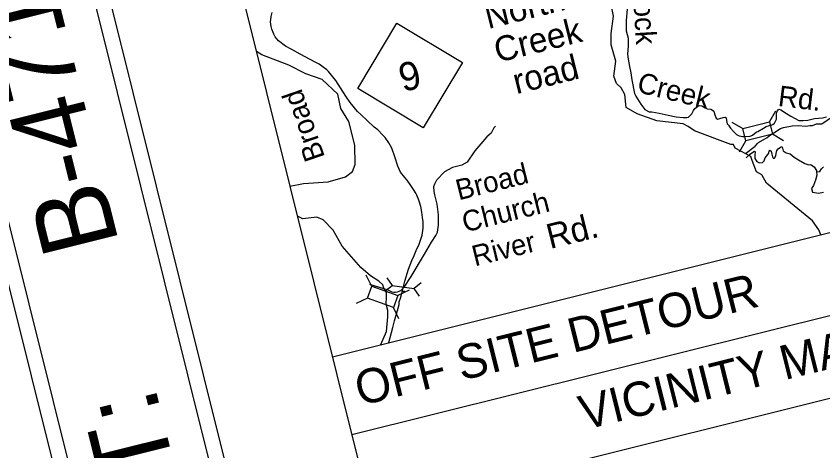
# Model space of a CAD drawing. Extents: x 1030323 to 1034123, y 654802 to 657751.
# Drawn here: x 1030543.2 to 1030807.6, y 656699.4 to 656841.8 of the extents above; entities that cross this region are included whole.
import ezdxf

# ---------------------------------------------------------------- set-up
doc = ezdxf.new("R2010")
doc.units = 0
for name, color, linetype in [('COGO Default Parcel', 7, 'Continuous'), ('Default', 7, 'Continuous'), ('Prop Dimension', 7, 'Continuous'), ('Prop Shade Light', 7, 'Continuous'), ('Sheet Title CELL', 7, 'Continuous')]:
    doc.layers.add(name, color=color, linetype=linetype)

msp = doc.modelspace()

# ---------------------------------------------------------------- linework, layer by layer
at = {"layer": 'COGO Default Parcel'}
for points in [[(1030763.46, 656805.71), (1030761.88, 656806.58), (1030753.15, 656807.52), (1030746.75, 656809.86), (1030743.2, 656811.93), (1030742.76, 656816.18), (1030741.52, 656818.34), (1030739.98, 656819.77), (1030739.15, 656822.21), (1030739.79, 656827.13), (1030738.2, 656832.4), (1030738.18, 656836.13), (1030738.96, 656841.88), (1030737.95, 656847.35), (1030734.88, 656851.54), (1030733.68, 656854.21), (1030732.33, 656861.16), (1030732.26, 656862.62), (1030731.76, 656863.61)], [(1030743.47, 656844.15), (1030743.19, 656840.4), (1030743.14, 656836.97), (1030743.76, 656834.57), (1030743.8, 656832.07), (1030743.61, 656829.36), (1030743.83, 656827.78), (1030744.26, 656825.33), (1030744.64, 656823.28), (1030745.01, 656820.98), (1030745.86, 656816.5), (1030746.32, 656815.6), (1030747.91, 656813.02), (1030749.3, 656811.27), (1030750.72, 656810.52), (1030751.58, 656810.48), (1030753.93, 656810.03), (1030756.89, 656809.38), (1030759.52, 656808.88), (1030761.86, 656808.63), (1030763.02, 656808.62), (1030763.59, 656808.78), (1030764.62, 656809.81), (1030765.22, 656810.88), (1030765.7, 656811.57), (1030766.53, 656812.27), (1030767.2, 656812.51), (1030767.99, 656812.49), (1030769.05, 656811.85), (1030769.75, 656811.51), (1030770.85, 656811.41), (1030771.46, 656811.04), (1030771.86, 656810.66), (1030772.25, 656809.46), (1030772.62, 656808.44), (1030773.13, 656808.12), (1030773.8, 656808.28), (1030774.98, 656808.62), (1030775.61, 656808.7), (1030775.88, 656808.55), (1030775.99, 656807.62), (1030776.21, 656806.6), (1030776.64, 656806.08), (1030777.33, 656805.14), (1030778.28, 656804.03), (1030779.27, 656803.09), (1030780.15, 656802.6), (1030781.25, 656802.37), (1030782.2, 656802.4), (1030783.75, 656802.5), (1030784.59, 656802.83), (1030785.81, 656803.82), (1030786.01, 656803.92)], [(1030674.54, 656783.15), (1030674.22, 656783.89), (1030674.04, 656784.19), (1030673.69, 656784.76), (1030673.27, 656785.35), (1030672.56, 656786.37), (1030671.37, 656788.07), (1030670.59, 656788.98), (1030669.24, 656790.73), (1030668.31, 656792.69), (1030667.28, 656795.77), (1030666.33, 656798.54), (1030665.41, 656800.29), (1030664.16, 656802.03), (1030663.36, 656802.86), (1030661.71, 656804.58), (1030660.6, 656805.5), (1030658.3, 656807.62), (1030656.18, 656809.63), (1030655.11, 656810.61), (1030652.71, 656813.59), (1030651.52, 656815.3), (1030650.32, 656817.11), (1030647.97, 656820.72), (1030645.57, 656823.73), (1030645.03, 656824.2), (1030643.88, 656825.17), (1030642.48, 656826.13), (1030641.44, 656826.7), (1030636.32, 656829.4), (1030633.57, 656830.89), (1030631.49, 656832.04), (1030629.19, 656833.77), (1030628.14, 656835.03), (1030627.69, 656835.97), (1030627.03, 656837.58), (1030626.82, 656838.47), (1030626.61, 656839.95), (1030626.67, 656840.69), (1030626.78, 656841.76), (1030627.15, 656843.07)], [(1030632.95, 656786.12), (1030637.35, 656787.05), (1030645.46, 656787.55), (1030651.15, 656789.22), (1030653.42, 656790.96), (1030654.34, 656793.19), (1030654.22, 656799.53), (1030652.25, 656807.28), (1030649.62, 656811.58), (1030648.61, 656816.31), (1030643.55, 656821.1), (1030638.19, 656822.93), (1030632.63, 656825.77), (1030623.69, 656829.12), (1030621.94, 656830.25)], [(1030786.01, 656803.92), (1030786.32, 656804.08), (1030788.12, 656805.11), (1030789, 656805.63), (1030790.17, 656806.02), (1030791.26, 656806.31), (1030791.79, 656806.8), (1030792.46, 656808.07), (1030792.45, 656808.66), (1030792.44, 656810.04), (1030792.61, 656810.74), (1030792.94, 656811.14), (1030793.31, 656811.35), (1030793.89, 656811.11), (1030795.73, 656809.9), (1030797.11, 656809.1), (1030799.78, 656807.61), (1030801.14, 656807.6), (1030802.72, 656807.72), (1030804.9, 656808.32), (1030806.15, 656808.44), (1030807.53, 656808.52), (1030808.85, 656808.83)], [(1030700.28, 656805.76), (1030699.75, 656805.27), (1030698.85, 656803.55), (1030697.53, 656802.26), (1030693.6, 656797.66), (1030690.99, 656794.05), (1030689.29, 656792.98), (1030686.22, 656792.28), (1030683.59, 656790.86), (1030681.05, 656788.22)], [(1030778.35, 656799.8), (1030777.43, 656799.78), (1030765.6, 656804.22), (1030763.46, 656805.71)], [(1030785.85, 656790.87), (1030784.43, 656794.58), (1030784, 656795.89), (1030778.91, 656798.64), (1030778.35, 656799.8)], [(1030806.92, 656770.19), (1030806.27, 656771.82), (1030804.24, 656774.79), (1030789.18, 656787.09), (1030787.65, 656789.86), (1030785.85, 656790.87)], [(1030659.02, 656753.99), (1030664.99, 656752.21), (1030666.39, 656751.55), (1030666.97, 656751.45), (1030667.57, 656751.43), (1030668.19, 656751.49), (1030669.25, 656751.94), (1030670.39, 656753.07), (1030672.67, 656756.5), (1030677.08, 656763.88), (1030679.3, 656767.75), (1030680.79, 656770), (1030681.33, 656771.12), (1030681.6, 656773.34), (1030681.68, 656776.78), (1030681.25, 656780.19), (1030680.41, 656783.25), (1030680.24, 656784.4), (1030680.16, 656785.98), (1030680.42, 656786.86), (1030681.05, 656788.22)], [(1030668.77, 656748.24), (1030669.14, 656749.48), (1030669.49, 656750.7), (1030670.63, 656755.04), (1030671.81, 656758.97), (1030672.94, 656761.83), (1030673.65, 656763.46), (1030674.27, 656765.03), (1030675.33, 656767.15), (1030676.27, 656770.12), (1030676.58, 656772.41), (1030676.67, 656773.41), (1030676.59, 656774.47), (1030676.39, 656775.89), (1030676.13, 656777.57), (1030675.8, 656779.49), (1030675.2, 656781.59), (1030674.54, 656783.15)], [(1030664.56, 656749.88), (1030664.6, 656751.22), (1030663.77, 656752.75), (1030663.38, 656753.82), (1030662.05, 656755.01), (1030659.33, 656756.74), (1030656.16, 656759.51), (1030650.02, 656766.51), (1030647.07, 656771.71), (1030643.82, 656775.15), (1030641.79, 656775.97), (1030637.19, 656775.44), (1030635.39, 656776.33)], [(1030662.79, 656734.25), (1030664.6, 656738.49), (1030665.05, 656743.34), (1030665.04, 656745.44), (1030664.47, 656747.53), (1030664.56, 656749.88)], [(1030665.39, 656734.9), (1030666.7, 656739.89), (1030667.25, 656742.07), (1030668.23, 656745.37), (1030668.71, 656747.35), (1030668.77, 656748.24)]]:
    msp.add_lwpolyline(points, dxfattribs=at)
at = {"layer": 'Default'}
for p, q in [((1030655.18, 656818.14), (1030668.04, 656839.55)), ((1030668.04, 656839.55), (1030689.46, 656826.69)), ((1030689.46, 656826.69), (1030676.59, 656805.27)), ((1030676.59, 656805.27), (1030655.18, 656818.14)), ((1030784.25, 656798.37), (1030784.26, 656798.38)), ((1030664.75, 656756.13), (1030666.49, 656753.65)), ((1030664.1, 656751.78), (1030666.49, 656753.65)), ((1030666.49, 656753.65), (1030673.63, 656752.6)), ((1030676.01, 656754.47), (1030673.63, 656752.6)), ((1030675.37, 656750.12), (1030673.63, 656752.6))]:
    msp.add_line(p, q, dxfattribs=at)
for points in [[(1030782.21, 656796.86), (1030785.44, 656799.25), (1030786.18, 656800.13), (1030786.53, 656800.43), (1030789.4, 656802.13), (1030790.45, 656802.95), (1030791.57, 656803.61), (1030793.73, 656805.01), (1030794.77, 656805.37), (1030797.6, 656805.9), (1030799.5, 656806.06), (1030802.01, 656805.83), (1030803.34, 656806.04), (1030804.24, 656806.03), (1030805.58, 656806.54), (1030806.02, 656806.6), (1030806.55, 656806.53), (1030807.26, 656806.53), (1030810.79, 656809)], [(1030786.01, 656803.92), (1030786.32, 656804.08), (1030788.12, 656805.11), (1030789, 656805.63), (1030790.17, 656806.02), (1030791.26, 656806.31), (1030791.79, 656806.8), (1030792.46, 656808.07), (1030792.45, 656808.66), (1030792.44, 656810.04), (1030792.61, 656810.74), (1030792.94, 656811.14), (1030793.31, 656811.35), (1030793.89, 656811.11), (1030795.73, 656809.9), (1030797.11, 656809.1), (1030799.78, 656807.61), (1030801.14, 656807.6), (1030802.72, 656807.72), (1030804.9, 656808.32), (1030806.15, 656808.44), (1030807.53, 656808.52), (1030808.85, 656808.83)], [(1030782.47, 656795.4), (1030783.6, 656796.48), (1030784.66, 656797.29), (1030785.18, 656797.59), (1030785.46, 656797.37), (1030785.31, 656796.28), (1030785.33, 656795.17), (1030786, 656794.2), (1030786.87, 656793.82), (1030787.81, 656793.91), (1030788.36, 656794.45), (1030788.76, 656795.37), (1030789.57, 656796.46), (1030789.87, 656796.96), (1030790.01, 656797.68), (1030790.26, 656797.94), (1030790.62, 656797.63), (1030790.87, 656796.64), (1030791.12, 656795.73), (1030791.38, 656795.26), (1030791.82, 656795.34), (1030792.21, 656796.06), (1030792.34, 656796.89), (1030792.58, 656797.78), (1030792.96, 656798.33), (1030793.77, 656798.96), (1030794.2, 656799.15), (1030794.42, 656798.64), (1030794.59, 656797.74), (1030795.57, 656797.01), (1030796.85, 656796.76), (1030798.16, 656795.64), (1030799.65, 656794.81), (1030801.76, 656793.57), (1030803.03, 656793.14), (1030803.6, 656793.24)], [(1030803.6, 656793.24), (1030804.82, 656792.46), (1030805.55, 656791.31), (1030805.57, 656790.83)], [(1030805.57, 656790.83), (1030805.62, 656789.78), (1030805.23, 656788.13), (1030804.55, 656786.41), (1030803.88, 656785.35), (1030804.26, 656784.2), (1030806.16, 656783.88), (1030807.87, 656784.13)], [(1030805.57, 656790.83), (1030806.61, 656790.96), (1030807.19, 656791.86), (1030807.87, 656792.51)], [(1030657.65, 656759.1), (1030657.65, 656759.1)], [(1030669.82, 656751.75), (1030670.11, 656751.73), (1030670.53, 656751.72), (1030670.61, 656751.72)]]:
    msp.add_lwpolyline(points, dxfattribs=at)
at = {"layer": 'Prop Shade Light'}
for p, q in [((1030790.12, 656807.25), (1030792.22, 656810.79)), ((1030777.83, 656807.14), (1030781.37, 656805.03)), ((1030791.13, 656803.25), (1030794.68, 656801.15)), ((1030780.31, 656797.41), (1030782.41, 656800.95)), ((1030659.75, 656753.3), (1030657.98, 656757.02)), ((1030671.99, 656752.11), (1030668.27, 656750.34)), ((1030658.37, 656749.42), (1030654.65, 656747.65)), ((1030668.62, 656742.66), (1030666.86, 656746.38))]:
    msp.add_line(p, q, dxfattribs=at)
for points in [[(1030781.37, 656805.03), (1030790.11, 656807.26), (1030791.15, 656803.18), (1030782.41, 656800.95)], [(1030666.86, 656746.38), (1030658.36, 656749.4), (1030659.77, 656753.37), (1030668.27, 656750.34)]]:
    msp.add_lwpolyline(points, close=True, dxfattribs=at)
at = {"layer": 'Sheet Title CELL'}
for p, q in [((1030789.97, 655960.36), (1030543.21, 656950.06)), ((1030750.07, 656141.07), (1030548.07, 656951.27)), ((1030597.29, 656929.11), (1030657.8, 656686.44)), ((1030646.87, 656730.28), (1030906.7, 656795.06)), ((1030653.23, 656704.76), (1030912.23, 656769.34)), ((1030666.87, 656681.06), (1030911.31, 656742.01))]:
    msp.add_line(p, q, dxfattribs=at)
for points in [[(1030493.49, 656942.81), (1030742.67, 655943.41)], [(1030499.56, 656939.18), (1030746.31, 655949.47)]]:
    msp.add_lwpolyline(points, dxfattribs=at)

# ---------------------------------------------------------------- texts
at = {"layer": 'Default'}
for s, height, rotation, p in [('North', 8.149, 14, (1030697.9, 656837.59)), ('Rock', 6.75, 273.3646, (1030745.19, 656852.91)), ('Creek', 8.149, 14, (1030701.04, 656826.56)), ('road', 8.149, 14, (1030707.15, 656816.26)), ('9', 9.28, 14, (1030669.98, 656816.92)), ('Creek', 6.75, 346.3118, (1030746.36, 656817.03)), ('Broad', 6.75, 109.0534, (1030644.49, 656795.66)), ('Rd.', 6.75, 353.0023, (1030792.69, 656812.45)), ('Broad', 6.75, 14, (1030688.25, 656781.47)), ('Church', 6.75, 14, (1030690.31, 656770.95)), ('Rd.', 8.149, 14, (1030718.2, 656765.52)), ('River', 6.75, 14, (1030693.55, 656759.84))]:
    msp.add_text(s, height=height, rotation=rotation, dxfattribs=at).set_placement(p)
at = {"layer": 'Prop Dimension'}
for s, p in [('OFF SITE DETOUR', (1030655.91, 656714.09)), ('VICINITY MAP', (1030729.41, 656706.2))]:
    msp.add_text(s, height=11.25, rotation=14, dxfattribs=at).set_placement(p)
at = {"layer": 'Sheet Title CELL'}
for s, p in [('  B-4715', (1030581.51, 656749.41)), ('TIP PROJECT:', (1030643.33, 656501.44))]:
    msp.add_text(s, height=25, rotation=104, dxfattribs=at).set_placement(p)

doc.saveas('drawing.dxf')
